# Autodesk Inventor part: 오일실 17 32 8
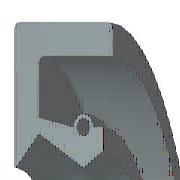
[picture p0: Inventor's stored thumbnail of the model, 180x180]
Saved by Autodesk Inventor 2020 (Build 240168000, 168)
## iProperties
Created: 2012-02
Part Number: 오일실 17 32 8
Material: 고무
Description: 오일-실
Document SubType Name: Modeling
Standard: KS B 2804
Designer: mduedu
Standards Organization: KS
Language: ko-KR
Size Designation: D - 17 32 8
Categories: <MemberInstance><Categories><Category DisplayName="샤프트 부품" InternalName="7f7aeb1f-a693-4053-b835-cee3144e0d98" Mnemonic="SHFT"><Category DisplayName="실링" Intern
Density: 0.93 g/cm^3
Appearance: 고무 - 검은색 - 버전 1.1
IsCustomPart: 1
Author: mduedu
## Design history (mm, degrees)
revolve "본체" stored, may be unused: angle "d17" = 90 deg
revolve "스프링1" stored, may be unused: angle "d18" = 90 deg
body "Solid1"
sketch "스케치1"
  geometry: L1 (0, 16)-(8, 16); L2 (8, 14.25)-(1.75, 14.25); L3 (1.75, 10.25)-(4.9, 8.5); L4 (4.9, 8.5)-(0, 8.5); L5 (0, 0)-(9.586, 0) reference; L6 (4.9, 8.5)-(6.3, 9.375); L7 (0, 18)-(0, -3) reference; L8 (-1.941, 0)-(11.507, 0) reference; L9 (4.2, 10.6)-(1.75, 11.21); L10 (1.75, 11.21)-(1.75, 14.25); L11 (0, 16)-(0, 8.588); L12 (4.9, 8.5)-(0, 8.5); L13 (1.75, 10.25)-(0.152, 8.528); L14 (8, 16)-(8, 14.25); L15 (5.6, 10.6)-(6.3, 10.6); L16 (6.3, 10.6)-(6.3, 9.375); C1 r 0.455 at (4.9, 10.6); A1 r 0.7 centre (4.9, 10.6) between (5.6, 10.6) and (4.2, 10.6); A2 r 0.088 centre (0.088, 8.588) between (0, 8.588) and (0.152, 8.528); 1 further point
  constraints: 28 end point, 5 horizontal alignment, 5 point on line, 4 point on circle, 4 vertical alignment, 3 centre point, 3 tangent, 2 collinear, 2 horizontal, 2 perpendicular, 1 coincident, 1 parallel
  dimensions: "d0" = 32 diameter of L1 L5 (= SD2); "d1" = 1.75 distance of L1.end L2.start (= SD); "d2" = 0.91 diameter of C1 (= SPDI); "d3" = 1.4 diameter of A1 (= SPDA); "d4" = 17 diameter of L3.end L5 (= NND); "d5" = 20.5 diameter of L3.start L5 (= TKDM); "d7" = 22.42 diameter of L9.end L5 (= TKDM + 0.24 x SWDT); "d8" = 1.75 distance between parallel lines of L11 L10 (= SD); "d9" = 4.9 distance from line of L11 C1.centre (= SPDST); "d10" = 21.2 diameter of C1.centre L5 (= HLDM); "d11" = 0.0875 radius of A2 (= 0.25 x LAB); "d12" = 6.3 distance between parallel lines of L11 L16 (= SDI); "d13" = 18.75 diameter of L6.end L5 (= ABDM); "d14" = 8 distance from line of L11 L1.end (= SWDT)
fillet "모깎기1" dims "d6" = 0.3 (= RR)
other parameters: "SD2" = 32 [user parameter; used in 1 equation term], "SWDT" = 8 [user parameter; used in 2 equation terms], "RR" = 0.3 [user parameter; used in 1 equation term], "SD" = 1.75 [user parameter; used in 2 equation terms], "NND" = 17 [user parameter; used in 1 equation term], "SPDA" = 1.4 [user parameter; used in 1 equation term], "SPDI" = 0.91 [user parameter; used in 1 equation term], "TKDM" = 20.5 [user parameter; used in 2 equation terms], "HLDM" = 21.2 [user parameter; used in 1 equation term], "ABDM" = 18.75 [user parameter; used in 1 equation term], "SDI" = 6.3 [user parameter; used in 1 equation term], "SPDST" = 4.9 [user parameter; used in 1 equation term], "LAB" = 0.35 [user parameter; used in 1 equation term], "d15" = 0, "d16" = 0, "d19" = 0
